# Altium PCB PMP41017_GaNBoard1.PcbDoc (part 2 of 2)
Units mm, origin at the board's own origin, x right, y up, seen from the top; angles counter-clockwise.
Board outline 21.11 x 35.1 mm, 4 copper layers (Top Layer, Layer 1, Layer 2, Bottom Layer), stack 1.926 mm thick; 24 components, 34 nets, 167 pads, 758 vias.
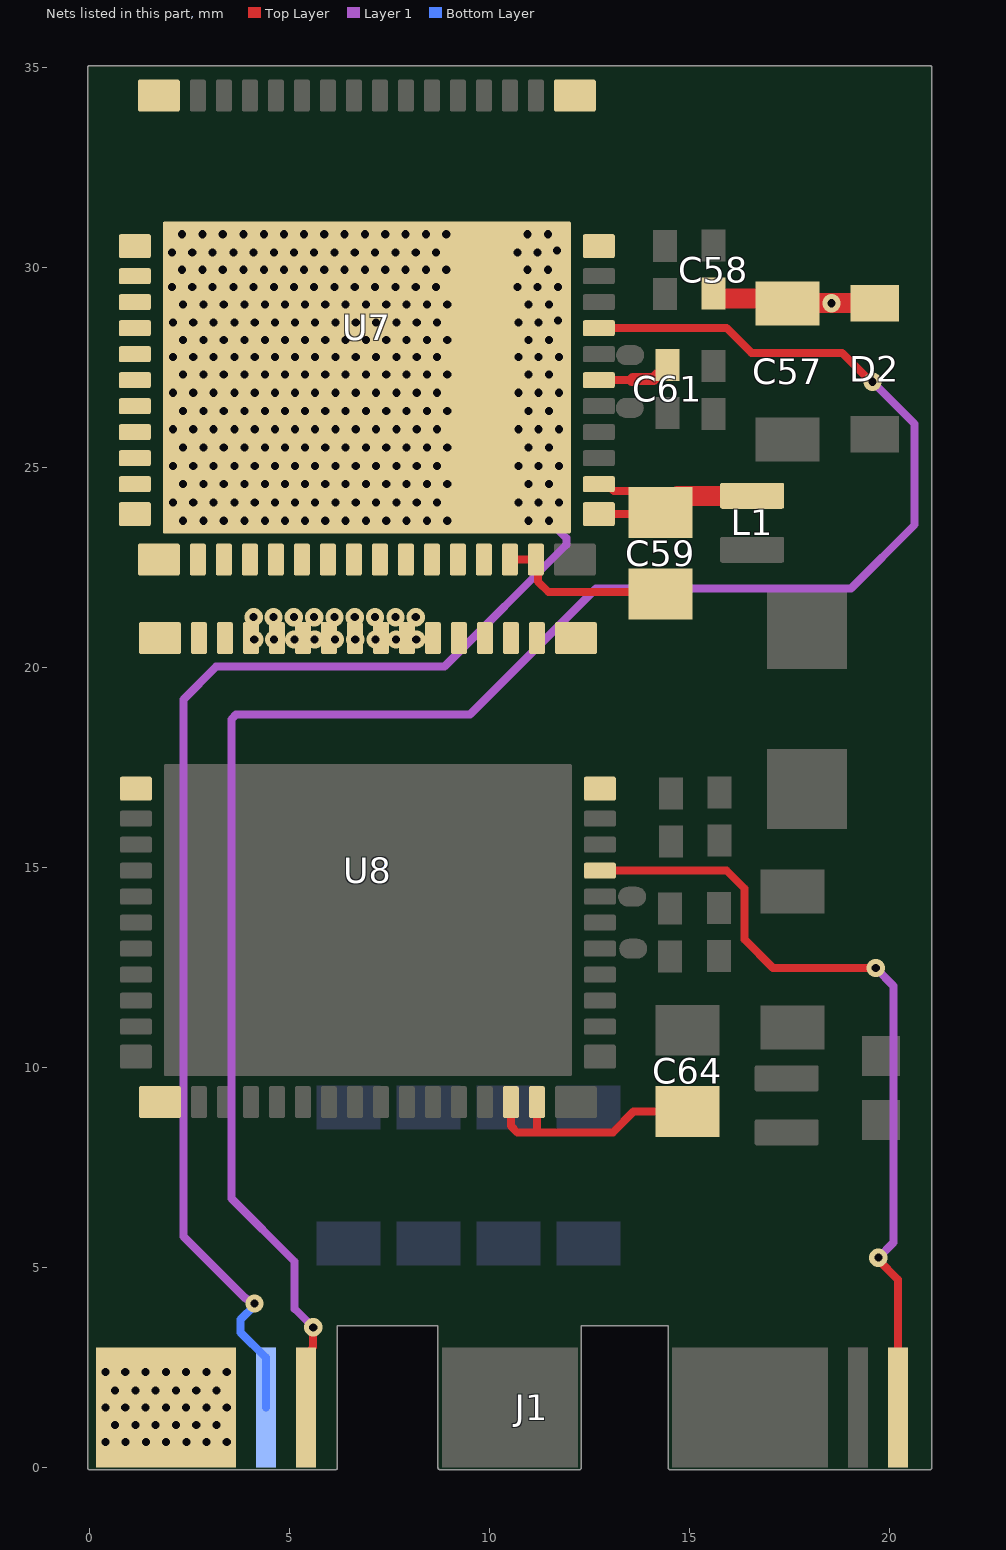
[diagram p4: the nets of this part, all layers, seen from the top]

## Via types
v1: diameter 0.457, hole 0.203, Top Layer to Bottom Layer, tented both sides, 758 vias

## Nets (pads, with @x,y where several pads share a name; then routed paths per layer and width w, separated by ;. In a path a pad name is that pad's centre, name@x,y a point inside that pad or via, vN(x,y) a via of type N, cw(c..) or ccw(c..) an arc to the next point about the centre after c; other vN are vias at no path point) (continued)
SW: C57.2 C58.2 C59.2 C61.1 D2.2 J1.8 J1.SW L1.1 U7.18 U7.19 U7.20 U7.21 U7.22 U7.23 U7.24 U7.25 U7.26 U7.27 U7.29 U7.30 U7.31 U7.32 U7.33 U7.34 U7.35 U7.36 U7.37 U7.38 U7.39 U7.40 U7.44 U7.45 U7.49 U7.55 U8.2 U8.3 U8.4 U8.5 U8.6 U8.7 U8.8 U8.9 U8.10 U8.11 U8.12 U8.13 U8.14 U8.15 | length 43.6
  Top Layer w0.2: U7.44@12.73,23.837 C59.2@14.646,23.837 ; U7.45@12.73,24.587 12.93,24.587 13.106,24.411 13.739,24.411 C59.2@14.274,23.876 C59.2@14.695,24.297 ; U7.49@12.73,27.187 13.562,27.187 ; C61.1@14.428,27.77 C61.1@14.428,27.87 ; L1.1@16.56,24.297 16.624,24.297 L1.1@16.799,24.472
  Top Layer w0.3: 13.562,27.187 13.588,27.213 14.094,27.213 14.2,27.319 14.3,27.319 14.45,27.469 C61.1@14.45,27.569
  Top Layer w0.5: C59.2@14.695,24.297 L1.1@16.56,24.297 ; C58.2@15.599,29.351 15.599,29.279 15.649,29.229 17.327,29.229 C57.2@17.449,29.108 17.451,29.11 v1(18.548,29.11) 19.626,29.11 D2.2@19.628,29.112
  Layer 1 w0.2: v1(4.12,4.104) 4.051,4.104 3.928,4.227 3.895,4.227 2.345,5.777 2.345,19.205 3.165,20.026 8.87,20.026 11.916,23.071 11.916,23.237 v1(11.48,23.673)
  Bottom Layer w0.2: v1(4.12,4.104) 4.12,4.047 3.775,3.702 3.775,3.38 4.405,2.75 J1.8@4.405,1.5
  other v1: 0.394,0.636 0.899,0.636 1.405,0.636 1.911,0.636 2.417,0.636 2.923,0.636 3.429,0.636 0.635,1.068 1.143,1.068 1.651,1.068 2.159,1.068 2.667,1.068 3.175,1.068 0.394,1.5 0.889,1.5 1.397,1.5 1.905,1.5 2.413,1.5 2.921,1.5 3.429,1.5 0.635,1.932 1.143,1.932 1.651,1.932 2.159,1.932 2.667,1.932 3.175,1.932 0.394,2.389 0.889,2.389 1.397,2.389 1.905,2.389 2.413,2.389 2.921,2.389 3.429,2.389 4.114,20.701 4.609,20.701 5.117,20.701 5.625,20.701 6.133,20.701 6.641,20.701 7.149,20.701 7.657,20.701 8.165,20.701 4.101,21.262 4.596,21.262 5.104,21.262 5.612,21.262 6.12,21.262 6.628,21.262 7.136,21.262 7.644,21.262 8.152,21.262 2.336,23.673 2.844,23.673 3.352,23.673 3.873,23.673 4.381,23.673 4.889,23.673 5.384,23.673 5.892,23.673 6.4,23.673 6.908,23.673 7.416,23.673 7.924,23.673 8.432,23.673 8.94,23.673 10.972,23.673 2.082,24.13 2.59,24.13 3.098,24.13 3.619,24.13 4.127,24.13 4.635,24.13 5.13,24.13 5.638,24.13 6.146,24.13 6.654,24.13 7.162,24.13 7.67,24.13 8.178,24.13 8.686,24.13 10.718,24.13 11.226,24.13 11.734,24.13 2.336,24.587 2.844,24.587 3.352,24.587 3.873,24.587 4.381,24.587 4.889,24.587 5.384,24.587 5.892,24.587 6.4,24.587 6.908,24.587 7.416,24.587 7.924,24.587 8.432,24.587 8.94,24.587 10.972,24.587 11.48,24.587 2.082,25.044 2.59,25.044 3.098,25.044 3.619,25.044 4.127,25.044 4.635,25.044 5.13,25.044 5.638,25.044 6.146,25.044 6.654,25.044 7.162,25.044 7.67,25.044 8.178,25.044 8.686,25.044 10.718,25.044 11.226,25.044 11.734,25.044 2.336,25.502 2.844,25.502 3.352,25.502 3.873,25.502 4.381,25.502 4.889,25.502 5.384,25.502 5.892,25.502 6.4,25.502 6.908,25.502 7.416,25.502 7.924,25.502 8.432,25.502 8.94,25.502 10.972,25.502 11.48,25.502 2.082,25.959 2.59,25.959 3.098,25.959 3.619,25.959 4.127,25.959 4.635,25.959 5.13,25.959 5.638,25.959 6.146,25.959 6.654,25.959 7.162,25.959 7.67,25.959 8.178,25.959 8.686,25.959 10.718,25.959 11.226,25.959 11.734,25.959 2.336,26.416 2.844,26.416 3.352,26.416 3.873,26.416 4.381,26.416 4.889,26.416 5.384,26.416 5.892,26.416 6.4,26.416 6.908,26.416 7.416,26.416 7.924,26.416 8.432,26.416 8.94,26.416 10.972,26.416 11.48,26.416 2.082,26.873 2.59,26.873 3.098,26.873 3.619,26.873 4.127,26.873 4.635,26.873 5.13,26.873 5.638,26.873 6.146,26.873 6.654,26.873 7.162,26.873 7.67,26.873 8.178,26.873 8.686,26.873 10.718,26.873 11.226,26.873 11.734,26.873 2.336,27.33 2.844,27.33 3.352,27.33 3.873,27.33 4.381,27.33 4.889,27.33 5.384,27.33 5.892,27.33 6.4,27.33 6.908,27.33 7.416,27.33 7.924,27.33 8.432,27.33 8.94,27.33 10.972,27.33 11.48,27.33 2.082,27.762 2.59,27.762 3.098,27.762 3.619,27.762 4.127,27.762 4.635,27.762 5.13,27.762 5.638,27.762 6.146,27.762 6.654,27.762 7.162,27.762 7.67,27.762 8.178,27.762 8.686,27.762 10.718,27.762 11.226,27.762 11.734,27.762 2.336,28.194 2.844,28.194 3.352,28.194 3.873,28.194 4.381,28.194 4.889,28.194 5.384,28.194 5.892,28.194 6.4,28.194 6.908,28.194 7.416,28.194 7.924,28.194 8.432,28.194 8.94,28.194 10.972,28.194 11.48,28.194 2.082,28.626 2.59,28.626 3.098,28.626 3.619,28.626 4.127,28.626 4.635,28.626 5.13,28.626 5.638,28.626 6.146,28.626 6.654,28.626 7.162,28.626 7.67,28.626 8.178,28.626 8.686,28.626 10.718,28.626 11.226,28.626 11.708,28.677 2.336,29.083 2.844,29.083 3.352,29.083 3.873,29.083 4.381,29.083 4.889,29.083 5.384,29.083 5.892,29.083 6.4,29.083 6.908,29.083 7.416,29.083 7.924,29.083 8.432,29.083 8.94,29.083 10.972,29.083 11.48,29.083 2.056,29.515 2.564,29.515 3.072,29.515 3.593,29.515 4.101,29.515 4.609,29.515 5.104,29.515 5.612,29.515 6.12,29.515 6.628,29.515 7.136,29.515 7.644,29.515 8.152,29.515 8.66,29.515 10.692,29.515 11.2,29.515 11.708,29.515 2.31,29.947 2.818,29.947 3.326,29.947 3.847,29.947 4.355,29.947 4.863,29.947 5.358,29.947 5.866,29.947 6.374,29.947 6.882,29.947 7.39,29.947 7.898,29.947 8.406,29.947 8.914,29.947 10.946,29.947 11.454,29.947 2.056,30.378 2.564,30.378 3.072,30.378 3.593,30.378 4.101,30.378 4.609,30.378 5.104,30.378 5.612,30.378 6.12,30.378 6.628,30.378 7.136,30.378 7.644,30.378 8.152,30.378 8.66,30.378 10.692,30.378 11.2,30.378 11.683,30.429 2.31,30.836 2.818,30.836 3.326,30.836 3.847,30.836 4.355,30.836 4.863,30.836 5.358,30.836 5.866,30.836 6.374,30.836 6.882,30.836 7.39,30.836 7.898,30.836 8.406,30.836 8.914,30.836 10.946,30.836 11.454,30.836
TEMP_H: J1.5 U7.51 | length 48.6
  Top Layer w0.2: J1.5@5.405,1.5 5.555,1.65 5.555,2.982 5.59,3.017 v1(5.59,3.507) ; U7.51@12.773,28.487 12.775,28.489 15.927,28.489 16.546,27.87 18.809,27.87 19.533,27.146 v1(19.571,27.146)
  Layer 1 w0.2: v1(5.59,3.507) 5.127,3.97 5.127,5.149 3.545,6.731 3.545,18.708 3.662,18.826 9.506,18.826 12.663,21.982 19.035,21.982 20.626,23.573 20.626,26.091 v1(19.571,27.146)
TEMP_L: J1.1 U8.51 | length 20.2
  Top Layer w0.2: U8.51@12.757,14.924 15.926,14.924 16.377,14.473 16.377,13.201 17.086,12.491 v1(19.653,12.491) ; v1(19.719,5.249) 19.719,5.191 20.205,4.704 J1.1@20.205,1.5
  Layer 1 w0.2: v1(19.653,12.491) 20.099,12.044 20.099,5.63 v1(19.719,5.249)
U1NC1: U7.1
U1NC16: U7.16
U1NC17: U7.17
U1NC28: U7.28
U1NC54: U7.54
U2NC1: U8.1
U2NC16: U8.16
U2NC17: U8.17
U2NC28: U8.28
U2NC54: U8.54
VNEG_H: C59.1 U7.41 U7.42 | length 5.1
  Top Layer w0.2: U7.41@10.505,22.702 U7.42@11.155,22.702 11.205,22.652 11.205,22.157 11.476,21.886 C59.1@14.819,21.886 ; C59.1@14.565,21.886 C59.1@14.646,21.805
VNEG_L: C64.1 U8.41 U8.42 | length 6.1
  Top Layer w0.2: U8.41@10.532,9.139 10.532,8.541 10.692,8.38 11.182,8.38 ; U8.42@11.182,9.139 11.182,8.38 ; C64.1@14.95,8.902 13.6,8.902 13.078,8.38 11.182,8.38

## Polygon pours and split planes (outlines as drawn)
PGND on Layer 2 "LAYER_2_PGND_P043" (solid, remove dead copper, pour order 43): 19.221,0 19.221,6.523 19.221,7.21 18.683,7.747 17.734,7.747 14.509,4.522 14.509,0
PGND on Layer 2 "LAYER_2_PGND_P028" (solid, remove dead copper, pour order 28): 12.187,17.719 12.216,13.513 10.359,13.513 10.359,17.535 10.543,17.719
SW on Layer 2 "LAYER_2_SW_P039" (solid, remove dead copper, pour order 39): 12.162,23.444 12.162,30.707 11.55,31.318 10.85,31.318 10.464,30.932 10.464,23.779 10.76,23.483
PGND on Layer 2 "LAYER_2_PGND_P027" (solid, remove dead copper, pour order 27): 12.242,9.797 12.214,13.772 10.359,13.772 10.359,10.081 10.643,9.797
PGND on Layer 2 "LAYER_2_PGND_P026" (solid, remove dead copper, pour order 26): 9.268,17.642 3.897,17.642 3.873,17.618 3.873,8.289 8.936,8.289 9.249,8.602
SW on Layer 2 "LAYER_2_SW_P025" (solid, remove dead copper, pour order 25): 9.324,31.109 9.324,22.782 8.767,22.225 8.767,20.299 8.66,20.193 4.863,20.193 3.545,18.875 3.545,4.053 4.005,3.594 4.005,0 0.05,0 0.05,30.076 1.13,31.156 9.276,31.156
HVBUS on Layer 2 "LAYER_2_HVBUS_P024" (solid, remove dead copper, pour order 24): 1.47,34.925 15.293,34.925 17.195,33.023 17.195,7.747 14.02,4.572 6.514,4.572 5.664,5.422 5.664,7.28 8.127,7.293 9.334,8.5 9.334,30.903 8.106,32.131 2.892,32.131 1.47,33.553
PGND on Layer 1 "LAYER_1_PGND_P042" (solid, remove dead copper, pour order 42): 20.812,17.907 10.731,17.907 10.359,17.535 10.359,10.053 10.799,9.613 18.826,9.613 20.812,11.599
HVBUS on Layer 1 "LAYER_1_HVBUS_P040" (solid, remove dead copper, pour order 40): 0.659,32.131 17.195,32.131 17.195,34.925 0.659,35
PGND on Layer 1 "Layer 1-PGND" (solid, remove dead copper, pour order 37): 19.376,5.612 19.376,9.086 19.065,9.397 10.687,9.397 10.58,9.441 10.102,9.919 10.058,10.026 10.058,17.907 4.378,17.907 3.926,17.455 3.926,8.515 5.243,7.198 13.966,7.198 14.782,6.382 14.782,0 18.505,0 19.065,0.56 19.065,5.301
SW on Layer 1 "LAYER_1_SW_P030" (solid, remove dead copper, pour order 30): 20.097,23.247 10.311,23.247 10.311,31.397 20.097,31.397
HVBUS on Layer 1 "LAYER_1_HVBUS_P034" (solid, remove dead copper, pour order 34): 12.347,0.204 12.347,2.569 13.512,3.734 13.512,6.35 5.664,6.35 5.664,5.422 6.514,4.572 6.896,4.572 8.432,3.036 8.432,0.219 8.447,0.204
SW on Layer 1 "LAYER_1_SW_P029" (solid, remove dead copper, pour order 29): 2.91,20.193 9.956,20.193 9.956,31.397 1.371,31.398 0.204,30.23 0.204,0 4.005,0 4.005,3.881 2.027,5.858 2.027,19.31
HVBUS on Bottom Layer "BOTTOM_LAYER_HVBUS_P023" (solid, remove dead copper, pour order 23): 13.504,0 8.556,0 8.556,3.074 5.664,5.966 5.664,6.35 13.504,6.35
PGND on Bottom Layer "Top Layer-PGND" (solid, remove dead copper, pour order 36): 20.655,7.01 19.699,7.01 18.576,5.887 18.576,0.914 18.297,0.635 14.909,0.635 14.782,0.762 14.782,7.198 13.576,8.404 0.638,8.404 0.204,8.838 0.204,17.719 0.392,17.907 10.356,17.907 20.655,17.907
HVBUS on Bottom Layer "BOTTOM_LAYER_HVBUS_P041" (solid, remove dead copper, pour order 41): 0.891,33.147 17.195,33.147 17.195,34.925 0.862,34.925
SW on Bottom Layer "BOTTOM_LAYER_SW_P033" (solid, remove dead copper, pour order 33): 0.832,31.318 19.044,31.318 20.097,30.265 20.097,21.862 17.789,19.553 1.113,19.553 0.204,20.463 0.204,30.69
SW on Top Layer "TOP_LAYER_SW_P031" (solid, remove dead copper, pour order 31): 12.91,31.398 1.723,31.398 0.59,30.265 0.59,21.914 2.31,20.193 12.91,20.193
HVBUS on Top Layer "TOP_LAYER_HVBUS_P032" (solid, remove dead copper, pour order 32): 2.194,33.147 17.195,33.147 17.195,34.925 2.164,34.925
PGND on Top Layer "TOP_LAYER_PGND_P035" (solid, remove dead copper, pour order 35): 12.807,8.315 12.807,17.907 0.392,17.907 0.204,17.719 0.204,8.637 0.526,8.315
HVBUS on Top Layer "TOP_LAYER_HVBUS_P038" (solid, remove dead copper, pour order 38): 12.348,0.204 12.348,3.035 13.512,4.199 13.512,5.966 13.128,6.35 5.664,6.35 5.664,5.706 6.798,4.572 8.433,2.937 8.433,0.219 8.448,0.204

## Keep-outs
Keep-Out Layer:
  text ".Layer_Name" at 1.016,-40.564 h1.52

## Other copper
Top Layer:
  region net PGND: 18.429,7.198 14.86,7.198 14.86,1.5 18.429,1.5
  text ".Layer_Name" at 3.299,-40.31 h1.52
Layer 1:
  text ".Layer_Name" at -1.27,-40.513 h1.52
Layer 2:
  text ".Layer_Name" at -2.032,-40.767 h1.52
Bottom Layer:
  pour cut-out: 16.733,10.399 ccw(c16.283,10.399) 15.833,10.399 ccw(c16.283,10.399)
  pour cut-out: 15.232,14.351 ccw(c14.782,14.351) 14.331,14.351 ccw(c14.782,14.351)
  pour cut-out: 17.455,13.54 ccw(c17.005,13.54) 16.555,13.54 ccw(c17.005,13.54)
  text ".Layer_Name" at -2.794,-40.64 h1.52

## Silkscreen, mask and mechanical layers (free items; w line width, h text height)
Top Overlay:
  text ".Layer_Name" at -3.829,-40.31 h1.52
Bottom Overlay:
  text ".Layer_Name" at -1.905,-40.386 h1.52
Top Paste:
  text ".Layer_Name" at -3.829,-40.31 h1.52
Bottom Paste:
  region: 8.94,30.988 5.94,30.988 5.94,27.988 8.94,27.988
  region: 5.257,30.988 2.257,30.988 2.257,27.988 5.257,27.988
  region: 8.94,24.257 8.94,27.257 5.94,27.257 5.94,24.257
  region: 5.257,24.257 5.257,27.257 2.257,27.257 2.257,24.257
  region: 8.94,20.749 8.94,23.749 5.94,23.749 5.94,20.749
  region: 5.257,20.749 5.257,23.749 2.257,23.749 2.257,20.749
  region: 13.893,20.749 13.893,23.749 10.893,23.749 10.893,20.749
  region: 17.576,20.749 17.576,23.749 14.576,23.749 14.576,20.749
  region: 13.893,24.257 13.893,27.257 10.893,27.257 10.893,24.257
  region: 17.576,24.257 17.576,27.257 14.576,27.257 14.576,24.257
  region: 13.893,30.988 10.893,30.988 10.893,27.988 13.893,27.988
  region: 17.576,30.988 14.576,30.988 14.576,27.988 17.576,27.988
  rectangle: 1.876,14.224 4.876,17.224
  rectangle: 1.876,10.541 4.876,13.541
  rectangle: 5.384,14.224 8.384,17.224
  rectangle: 5.384,10.541 8.384,13.541
  region: 12.115,14.224 12.115,17.224 9.115,17.224 9.115,14.224
  region: 12.115,10.541 12.115,13.541 9.115,13.541 9.115,10.541
  text ".Layer_Name" at -2.867,-40.922 h1.52
Top Solder:
  text ".Layer_Name" at -4.141,-40.386 h1.52
  text ".Layer_Name" at -4.141,-40.386 h1.52
Bottom Solder:
  region: 12.496,9.919 12.496,17.919 1.496,17.919 1.496,9.919
  region: 18.177,31.385 10.177,31.385 10.177,20.385 18.177,20.385
  region: 9.451,31.318 1.451,31.318 1.451,20.318 9.451,20.318
  text ".Layer_Name" at -2.867,-40.922 h1.52
Drill Guide:
  text ".Layer_Name" at 1.016,-40.564 h1.52
M1 Board Outline:
  lines w0.1: 0,0 0,35 ; 0.005,0.165 0.005,0 6.146,0 6.146,3.6 8.759,3.6 8.759,0 12.242,0 12.242,3.6 14.514,3.6 14.514,0 21.005,0 21.005,35 ; 0,35 ccw(c0,35) 0,35 ; 0,35 21.005,35 ; 21.005,35 ccw(c21.005,35) 21.005,35 ; 21.005,35 21.005,35
  text ".Layer_Name" at 117.983,-40.894 h1.52
M2 Board Dimensions:
  region: 22.603,-13.147 19.428,-13.147 19.428,-16.322 22.603,-16.322
  region: 19.428,-16.322 9.903,-16.322 9.903,-19.497 19.428,-19.497
  lines w0.178: -2.797,-16.322 22.603,-16.322 ; 3.553,-19.497 3.553,-13.147 ; 9.903,-19.497 9.903,-13.147 ; 16.253,-19.497 16.253,-13.147 ; 19.428,-19.497 19.428,-13.147 ; -2.797,-19.497 22.603,-19.497 22.603,-13.147 -2.797,-13.147 -2.797,-19.497
  text ".Layer_Name" at -5.588,-40.894 h1.52
M3 3D STEP Top:
  text ".Layer_Name" at 118.872,-41.021 h1.52
M4 3D STEP Bottom:
  text ".Layer_Name" at 117.983,-41.148 h1.52
M5 Assembly Top:
  lines w0.254: -27.153,-42.511 140.487,-42.511 ; -27.153,-37.346 140.538,-37.346 ; -27.153,-32.182 -27.153,-47.676 74.574,-47.676 140.538,-47.676 140.538,-32.182 -27.14,-32.182 -27.14,-47.676 12.878,-47.676 ; 35.458,-47.676 35.458,-32.182 ; 67.64,-37.346 67.64,-32.182 ; 88.976,-37.346 88.976,-32.182 ; 104.775,-47.841 104.775,-42.689
  text "COMPONENTS MARKED 'DNP' SHOULD NOT BE POPULATED." at 9.563,-26.975 h1.52
  text "ASSEMBLY VARIANT:" at 9.55,-29.908 h1.52
  text ".VariantName" at 35.865,-29.908 h1.52
  text "PCB VIEWED FROM TOP SIDE" at -25.54,-35.539 h1.52
  text "BOARD #:" at 37.363,-35.539 h1.52
  text ".PRJ_Number" at 51.219,-35.539 h1.52
  text "REV:" at 72.669,-35.539 h1.52
  text ".PCB_Rev" at 80.073,-35.539 h1.52
  text "SVN REV:" at 93.955,-35.539 h1.52
  text ".VersionControl_RevNumber" at 106.807,-35.539 h1.52
  text "TID #:" at 37.363,-40.704 h1.52
  text ".TID" at 51.219,-40.704 h1.52
  text "PLOT NAME =" at -25.54,-45.919 h1.52
  text "PMP41017_GaNBoard" at -5.08,-45.919 h1.52
  text "GENERATED    :" at 37.414,-45.919 h1.52
  text ".Print_Date" at 59.499,-45.919 h1.52
  text ".Print_Time" at 78.016,-45.919 h1.52
  text "TEXAS INSTRUMENTS" at 110.134,-45.919 h1.52
M6 Assembly Bottom:
  lines w0.254: -27.165,-37.359 140.525,-37.359 ; -27.114,-42.524 140.525,-42.524 ; 8.598,-47.854 8.598,-42.702 ; 24.397,-37.359 24.397,-32.195 ; 45.733,-37.359 45.733,-32.195 ; 77.915,-47.688 77.915,-32.195 ; 100.495,-47.688 140.513,-47.688 140.513,-32.194 -27.165,-32.195 -27.165,-47.688 38.798,-47.688 140.525,-47.688 140.525,-32.194
  text "COMPONENTS MARKED 'DNP' SHOULD NOT BE POPULATED." at 135.255,-26.962 h1.52
  text ".VariantName" at 108.737,-29.908 h1.52
  text "ASSEMBLY VARIANT:" at 135.128,-29.908 h1.52
  text ".VersionControl_RevNumber" at 6.566,-35.552 h1.52
  text "SVN REV:" at 19.418,-35.552 h1.52
  text ".PCB_Rev" at 33.299,-35.552 h1.52
  text "REV:" at 40.703,-35.552 h1.52
  text "BOARD #:" at 76.01,-35.552 h1.52
  text "PCB VIEWED FROM BOTTOM SIDE" at 138.913,-35.552 h1.52
  text "PMP41017_GaN" at 64.008,-35.687 h1.52
  text ".TID" at 62.154,-40.716 h1.52
  text "TID #:" at 76.01,-40.716 h1.52
  text "TEXAS INSTRUMENTS" at 3.238,-45.932 h1.52
  text ".Print_Time" at 35.357,-45.932 h1.52
  text ".Print_Date" at 53.873,-45.932 h1.52
  text "GENERATED    :" at 75.959,-45.932 h1.52
  text "PMP41017_GaNBoard" at 118.453,-45.932 h1.52
  text "PLOT NAME =" at 138.913,-45.932 h1.52
M9 Title Sheet:
  drawing of 57 lines, arcs and shapes, not listed
  text "1" at -16.207,166.469 h1.78
  text "2" at 47.183,166.469 h1.78
  text "3" at 110.412,166.469 h1.78
  text "4" at 174.081,166.469 h1.78
  text "5" at 237.556,166.469 h1.78
  text "6" at 301.183,166.469 h1.78
  text "A" at -45.578,137.436 h1.78
  text "A" at 330.342,137.436 h1.78
  text "B" at -45.578,76.984 h1.78
  text "B" at 330.342,76.984 h1.78
  text "C" at -45.578,16.659 h1.78
  text "C" at 330.342,16.659 h1.78
  text "PROJECT TITLE:" at 253.126,-30.61 h1.14
  text ".PRJ_Title" at 254.396,-33.996 h1.78
  text "DESIGNED FOR:" at 253.126,-38.255 h1.14
  text ".Layer_Name" at -3.556,-40.64 h1.52
  text ".PRJ_Customer" at 254.396,-41.811 h1.78
  text "D" at -45.578,-43.539 h1.78
  text "D" at 330.342,-43.539 h1.78
  text "FILE NAME:" at 253.126,-45.875 h1.14
  text ".PCB_File_Name_No_Path" at 254.396,-48.923 h1.78
  text "Texas Instruments (TI) and/or its licensors do not warrant the accuracy or completeness of this specification" at 126.9,-53.034 h1.14
  text "ENGINEER:" at 253.126,-53.241 h1.14
  text "LAYOUT BY:" at 291.353,-53.241 h1.14
  text "or any information contained therein. TI and/or its licensors do not warrant that this design will meet" at 125.758,-55.896 h1.14
  text ".PRJ_Engineer" at 254.396,-57.178 h1.78
  text ".PCB_Layout" at 292.635,-57.178 h1.78
  text "the specifications, will be suitable for your application or fit for any particular purpose, or will operate in" at 125.758,-58.757 h1.14
  text "ALTIUM DESIGNER VERSION:" at 291.353,-61.115 h1.14
  text "an implementation. TI and/or its licensors do not warrant that the design is production worthy. You should" at 125.758,-61.619 h1.14
  text "completely validate and test your design implementation to confirm the system functionality for your application." at 126.9,-64.481 h1.14
  text ".print_Scale" at 254.396,-64.502 h1.78
  text ".Application_BuildNumber" at 292.635,-64.502 h1.78
  text "1" at -16.207,-69.751 h1.78
  text "2" at 47.183,-69.751 h1.78
  text "3" at 110.412,-69.751 h1.78
  text "4" at 174.081,-69.751 h1.78
  text "5" at 237.556,-69.751 h1.78
  text "6" at 301.183,-69.751 h1.78
M10 Fab Notes:
  drawing of 189 lines, arcs and shapes, not listed
  text "DESIGN INFORMATION" at 265.725,143.895 h1.52
  text "MIN. TRACK WIDTH:" at 249.353,140.539 h1.52
  text "8" at 277.198,140.54 h1.52
  text "MIL" at 281.129,140.539 h1.52
  text "7.874" at 272.972,137.449 h1.52
  text "MIN. CLEARANCE:" at 249.353,137.387 h1.52
  text "MIL" at 281.129,137.387 h1.52
  text "MIN. VIA PAD SIZE:" at 249.353,134.234 h1.52
  text "24" at 276.436,134.234 h1.52
  text "MIL" at 281.129,134.234 h1.52
  text "0.05mm (2MIL)" at 267.006,130.934 h1.52
  text "MINIMUM ANNULAR RING" at 240.991,130.726 h1.52
  text "EXTERNAL" at 284.99,130.726 h1.52
  text "PER" at 246.071,127.928 h1.52
  text "IPC-D-275 CLASS 2 LEVEL C" at 251.659,127.928 h1.52
  text "MIL, HOLES" at 289.46,125.376 h1.52
  text "+/-" at 279.492,125.158 h1.52
  text "+/-" at 301.183,125.158 h1.52
  text "REGISTRATION TOLERANCES:" at 240.991,125.131 h1.52
  text "METAL" at 271.465,125.131 h1.52
  text "5" at 286.101,125.131 h1.52
  text "3" at 307.259,125.131 h1.52
  text "MIL" at 310.212,125.131 h1.52
  text "HOLE SIZE TOLERANCE (UNLESS OTHERWISE SPECIFIED):" at 240.991,122.634 h1.52
  text "+/-" at 301.183,122.561 h1.52
  text "3" at 307.259,122.534 h1.52
  text "MIL" at 310.212,122.534 h1.52
  text "MATERIAL:" at 239.092,119.038 h1.52
  text "FR-4 High Tg" at 264.148,115.773 h1.52
  text "X" at 260.479,115.57 h1.52
  text "FR-408" at 249.785,115.455 h1.52
  text "OTHER" at 287.58,115.455 h1.52
  text "62 MIL (1.6mm) +/-10%" at 257.916,111.822 h1.52
  text "X" at 254.865,111.76 h1.52
  text "THICKNESS:" at 240.991,111.614 h1.52
  text "OTHER" at 290.552,111.614 h1.52
  text "TOLERANCE:" at 240.991,108.1 h1.52
  text "X" at 262.536,108.1 h1.52
  text "ANSI IPC-6012 TYPE 3 CLASS 2" at 267.058,108.1 h1.52
  text "OTHER +/-" at 267.057,104.438 h1.52
  text "BOW & TWIST:" at 240.991,100.75 h1.52
  text "X" at 262.536,100.75 h1.52
  text "ANSI IPC-6012 TYPE 3 CLASS 2" at 267.058,100.75 h1.52
  text "OTHER +/-" at 267.057,97.024 h1.52
  text "DRILLING:" at 239.092,93.706 h1.52
  text "NC_DRILL FILES" at 283.821,91.035 h1.52
  text "REFERENCE:" at 240.991,90.935 h1.52
  text "X" at 257.685,90.932 h1.52
  text "AS SHOWN" at 262.206,90.935 h1.52
  text "X" at 280.57,90.935 h1.52
  text "OTHER" at 291.39,87.321 h1.52
  text "PTH COPPER THICKNESS:" at 240.983,87.232 h1.52
  text "X" at 269.919,87.232 h1.52
  text "20-30 um" at 273.17,87.232 h1.52
  text "BOARD FINISH:" at 239.092,83.483 h1.52
  text "SILKSCREEN:" at 243.035,80.686 h1.52
  text "X" at 267.362,80.686 h1.52
  text "TOP" at 270.334,80.686 h1.52
  text "X" at 280.316,80.686 h1.52
  text "BOTTOM" at 283.313,80.686 h1.52
  text "SILKSCREEN COLOR:" at 243.035,76.744 h1.52
  text "X" at 267.337,76.744 h1.52
  text "WHITE" at 270.334,76.744 h1.52
  text "OTHER" at 283.313,76.744 h1.52
  text "X" at 270.664,73.1 h1.52
  text "GREEN" at 273.661,73.1 h1.52
  text "OTHER" at 289.358,73.1 h1.52
  text "SOLDER RESIST COLOR:" at 243.035,72.926 h1.52
  text "X" at 270.664,69.182 h1.52
  text "MATTE" at 273.661,69.182 h1.52
  text "SEMI-GLOSS" at 289.347,69.166 h1.52
  text "IMMERSION GOLD (ENIG)" at 266.041,64.794 h1.52
  text "ENEPIG" at 300.015,64.61 h1.52
  text "SURFACE FINISH:" at 239.092,64.585 h1.52
  text "X" at 261.52,64.585 h1.52
  text "IMM. TIN/SILVER OR EQUIV" at 247.462,61.097 h1.52
  text "OTHER" at 283.821,60.997 h1.52
  text "ARRAY/PANEL:" at 239.092,57.051 h1.52
  text "CUT AND TRIM PER M1 BOARD OUTLINE" at 266.041,56.842 h1.52
  text "N.C. ROUTE" at 266.041,53.388 h1.52
  text "X" at 283.517,53.388 h1.52
  text "V. SCORE" at 288.038,53.388 h1.52
  text "CERTIFICATION:" at 239.092,50.108 h1.52
  text "MATERIALS AND WORKMANSHIP FOR ALL PCBS" at 257.507,50.108 h1.52
  text "TO MEET OR EXCEED THE REQUIREMENTS OF:" at 257.507,47.719 h1.52
  text "X" at 248.3,44.452 h1.52
  text "ANSI IPC-A-600F CLASS ->" at 251.551,44.452 h1.52
  text "X" at 293.41,44.452 h1.52
  text "2" at 296.204,44.452 h1.52
  text "1" at 288.203,44.414 h1.52
  text "3" at 305.195,44.414 h1.52
  text "X" at 268.924,40.701 h1.52
  text "RoHS" at 272.175,40.701 h1.52
  text "OTHER" at 288.543,40.701 h1.52
  text "PER ORDER" at 298.629,40.701 h1.52
  text "ALL BOARDS MUST MEET OR EXCEED UL94-V0 REQUIREMENTS." at 239.791,36.794 h1.52
  text "PCB MUST BEAR THE UL94V-0 UL REGISTERED MATERIAL ID NUMBER" at 239.791,33.846 h1.52
  text "ADDITIONAL REQUIREMENTS:" at 239.092,29.542 h1.52
  text "MICROSECTION:" at 240.991,26.821 h1.52
  text "YES" at 263.997,26.821 h1.52
  text "REQUIRED" at 285.879,23.155 h1.52
  text "BARE BOARD ELEC. TEST:" at 240.991,23.083 h1.52
  text "NONE" at 274.157,23.083 h1.52
  text "X" at 282.882,23.083 h1.52
  text "PER ORDER" at 300.915,23.083 h1.52
  text "XX MIL VIAS REQUIRE NON-CONDUCTIVE FILL AND PLANARIZE" at 245.262,17.877 h1.5
  text "XX MIL VIAS REQUIRE CONDUCTIVE FILL AND PLANARIZE" at 245.465,15.236 h1.52
  text "OUTER XX MIL TRACES REQUIRE 50 OHM SINGLE-ENDED IMPEDANCE" at 245.44,11.086 h1.47
  text "LAYER 2 & 3 (INNER LAYERS) XX MIL WIDE, XX MIL SPACE / TRACES REQUIRE 100 OHM DIFFERENTIAL IMPEDANCE" at 245.237,5.099 h1.52
  text ".Layer_Name" at 108.585,-40.64 h1.52
M11 Gerber Information:
  lines w0.254: -27.114,-42.587 140.525,-42.587 ; -27.114,-37.423 140.576,-37.423 ; -27.114,-32.258 -27.114,-47.752 74.612,-47.752 140.576,-47.752 140.576,-32.258 -27.102,-32.258 -27.102,-47.752 12.916,-47.752 ; 35.496,-47.752 35.496,-32.258 ; 67.678,-37.423 67.678,-32.258 ; 89.014,-37.423 89.014,-32.258 ; 104.813,-47.917 104.813,-42.765
  text "ALL ARTWORK VIEWED FROM TOP SIDE" at -25.502,-35.615 h1.52
  text "BOARD #:" at 37.401,-35.615 h1.52
  text "PMP41017_GaN" at 51.257,-35.615 h1.3
  text "REV:" at 72.707,-35.615 h1.52
  text ".PCB_Rev" at 80.112,-35.615 h1.52
  text "SVN REV:" at 93.993,-35.615 h1.52
  text ".VersionControl_RevNumber" at 106.845,-35.615 h1.52
  text "LAYER NAME =" at -25.502,-40.767 h1.52
  text "TID #:" at 37.401,-40.78 h1.52
  text ".TID" at 51.257,-40.78 h1.52
  text "PLOT NAME =" at -25.502,-45.995 h1.52
  text "PMP41017_GaNBoard" at -5.042,-45.995 h1.52
  text "GENERATED    :" at 37.452,-45.995 h1.52
  text ".Print_Date" at 59.538,-45.995 h1.52
  text ".Print_Time" at 78.054,-45.995 h1.52
  text "TEXAS INSTRUMENTS" at 110.172,-45.995 h1.52
M12 Stackup:
  drawing of 297 lines, arcs and shapes, not listed
  text "Layer" at 23.242,105.85 h1.52
  text "Name" at 33.654,105.85 h1.52
  text "Material" at 57.269,105.85 h1.52
  text "Thickness" at 79.107,105.85 h1.52
  text "Constant" at 95.613,105.85 h1.52
  text "Board Layer Stack" at 110.088,105.85 h1.52
  text "Top Overlay" at 33.654,102.802 h1.52
  text "Top Solder" at 33.654,99.754 h1.52
  text "Solder Resist" at 57.269,99.754 h1.52
  text "0.40mil" at 79.107,99.754 h1.52
  text "3.5" at 95.613,99.754 h1.52
  text "1" at 23.242,96.706 h1.52
  text "Top Layer" at 33.654,96.706 h1.52
  text "CF-005" at 57.269,96.706 h1.52
  text "2.76mil" at 79.107,96.706 h1.52
  text "Dielectric 1" at 33.654,93.658 h1.52
  text "PP-006" at 57.269,93.658 h1.52
  text "2.80mil" at 79.107,93.658 h1.52
  text "4.1" at 95.613,93.658 h1.52
  text "2" at 23.242,90.61 h1.52
  text "Layer 1" at 33.654,90.61 h1.52
  text "CF-005" at 57.269,90.61 h1.52
  text "2.76mil" at 79.107,90.61 h1.52
  text "Dielectric1" at 33.654,87.562 h1.52
  text "FR-4 High Tg" at 57.269,87.562 h1.52
  text "59.20mil" at 79.107,87.562 h1.52
  text "4.8" at 95.613,87.562 h1.52
  text "3" at 23.242,84.514 h1.52
  text "Layer 2" at 33.654,84.514 h1.52
  text "CF-005" at 57.269,84.514 h1.52
  text "2.76mil" at 79.107,84.514 h1.52
  text "Dielectric 2" at 33.654,81.466 h1.52
  text "PP-006" at 57.269,81.466 h1.52
  text "2.80mil" at 79.107,81.466 h1.52
  text "4.1" at 95.613,81.466 h1.52
  text "4" at 23.242,78.418 h1.52
  text "Bottom Layer" at 33.654,78.418 h1.52
  text "CF-005" at 57.269,78.418 h1.52
  text "2.76mil" at 79.107,78.418 h1.52
  text "Bottom Solder" at 33.654,75.37 h1.52
  text "Solder Resist" at 57.269,75.37 h1.52
  text "0.40mil" at 79.107,75.37 h1.52
  text "3.5" at 95.613,75.37 h1.52
  text "Bottom Overlay" at 33.654,72.322 h1.52
  text ".Layer_Name" at 117.348,-40.894 h1.52
M13 Component Bodies Top:
  text ".Layer_Name" at 119.253,-40.64 h1.52
M14 Component Bodies Bottom:
  text ".Layer_Name" at 118.237,-40.767 h1.52
M15 Courtyards Top:
  text ".Layer_Name" at 117.602,-40.894 h1.52
M16 Courtyards Bottom:
  text ".Layer_Name" at 118.872,-40.767 h1.52
Drill Drawing:
  lines w0.254: 55.342,63.187 56.044,62.485 56.746,63.187 56.044,63.888 55.342,63.187
  lines w0.305: 54.07,61.538 136.15,61.538 ; 54.07,64.695 136.15,64.695 ; 62.652,58.38 62.652,67.853 ; 71.084,58.38 71.084,67.853 ; 87.253,58.38 87.253,67.853 ; 93.835,58.38 93.835,67.853 ; 103.364,58.38 103.364,67.853 ; 121.762,58.38 121.762,67.853 ; 54.07,58.38 136.15,58.38 136.15,67.853 54.07,67.853 54.07,58.38
  text "Symbol" at 55.965,65.643 h1.83
  text "Quantity" at 63.599,65.643 h1.83
  text "Finished Hole Size" at 72.032,65.643 h1.83
  text "Plated" at 88.2,65.643 h1.83
  text "Hole Type" at 94.783,65.643 h1.83
  text "Drill Layer Pair" at 104.312,65.643 h1.83
  text "Hole Tolerance" at 122.71,65.643 h1.83
  text "758" at 63.599,62.485 h1.52
  text "8.00mil (0.203mm)" at 72.032,62.485 h1.52
  text "PTH" at 88.2,62.485 h1.52
  text "Round" at 94.783,62.485 h1.52
  text "Top Layer - Bottom Layer" at 104.312,62.485 h1.52
  text "758 Total" at 63.599,59.327 h1.52
  text ".Layer_Name" at 1.016,-40.564 h1.52
M17 Embedded Cavity:
  text ".Layer_Name" at 90.043,-41.148 h1.52
M18 Embedded Assembly:
  text ".Layer_Name" at 87.884,-40.691 h1.52
M19 Embedded Keepout:
  lines w1.2: -1.855,4.445 13.545,4.445
  text ".Layer_Name" at 90.297,-40.818 h1.52

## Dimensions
14.355,0 to 0,35 on M2 Board Dimensions
21.005,35 to 0,35 on M2 Board Dimensions
22.603,-19.497 to -2.797,-19.497 on M2 Board Dimensions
